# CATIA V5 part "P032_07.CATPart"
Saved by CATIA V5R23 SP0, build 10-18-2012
Part number: 05-LICP-T02-E-S06-P032_07
Bounding box of the stored display mesh (mm): x 1.387 to 1.837, y -14.784 to 14.784, z -14.784 to 14.784
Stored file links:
  C:\wamp\www\COURS\CONCEPTION GMP1\TITRE 02-SEMESTRE 2\03-TP7-PRESSE MECANIQUE\eleve\P032_07.CATPart
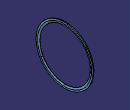
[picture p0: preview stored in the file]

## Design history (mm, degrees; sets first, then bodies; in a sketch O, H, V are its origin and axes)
Body1 (main body)
  Solid1: solid without history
